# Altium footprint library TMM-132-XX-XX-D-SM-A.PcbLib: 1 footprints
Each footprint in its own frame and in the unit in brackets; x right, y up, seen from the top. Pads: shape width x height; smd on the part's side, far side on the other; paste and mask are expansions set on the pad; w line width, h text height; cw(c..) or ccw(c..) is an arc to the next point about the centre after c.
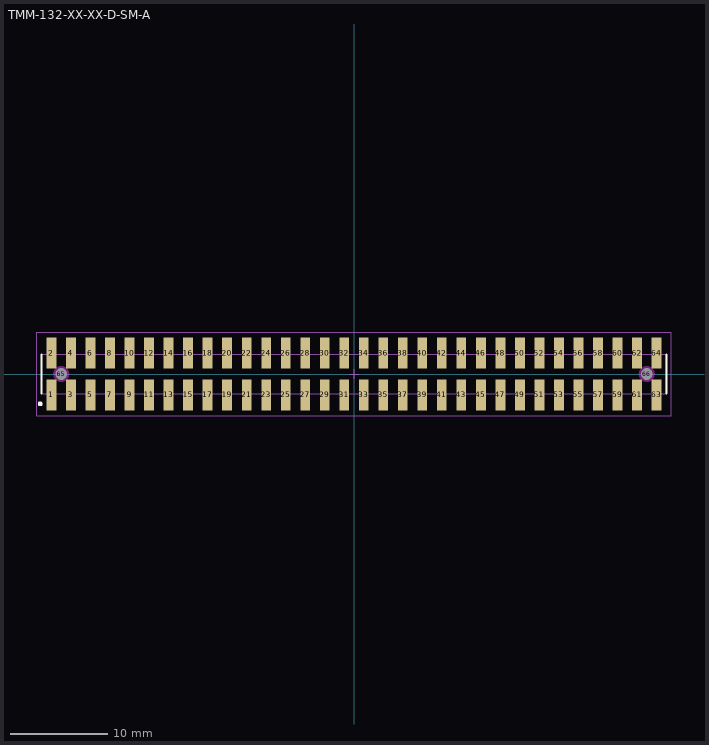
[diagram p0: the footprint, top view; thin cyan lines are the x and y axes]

## TMM-132-XX-XX-D-SM-A [mm] "2.00mm pitch, 64 pin, terminal strip; double row, w/alignment pins, SMT"
height 2.77
pads (66):
  rect 1x3.2 smd mask+0: 1(-31,-2.15) 2(-31,2.15) 3(-29,-2.15) 4(-29,2.15) 5(-27,-2.15) 6(-27,2.15) 7(-25,-2.15) 8(-25,2.15) 9(-23,-2.15) 10(-23,2.15) 11(-21,-2.15) 12(-21,2.15) 13(-19,-2.15) 14(-19,2.15) 15(-17,-2.15) 16(-17,2.15) 17(-15,-2.15) 18(-15,2.15) 19(-13,-2.15) 20(-13,2.15) 21(-11,-2.15) 22(-11,2.15) 23(-9,-2.15) 24(-9,2.15) 25(-7,-2.15) 26(-7,2.15) 27(-5,-2.15) 28(-5,2.15) 29(-3,-2.15) 30(-3,2.15) 31(-1,-2.15) 32(-1,2.15) 33(1,-2.15) 34(1,2.15) 35(3,-2.15) 36(3,2.15) 37(5,-2.15) 38(5,2.15) 39(7,-2.15) 40(7,2.15) 41(9,-2.15) 42(9,2.15) 43(11,-2.15) 44(11,2.15) 45(13,-2.15) 46(13,2.15) 47(15,-2.15) 48(15,2.15) 49(17,-2.15) 50(17,2.15) 51(19,-2.15) 52(19,2.15) 53(21,-2.15) 54(21,2.15) 55(23,-2.15) 56(23,2.15) 57(25,-2.15) 58(25,2.15) 59(27,-2.15) 60(27,2.15) 61(29,-2.15) 62(29,2.15) 63(31,-2.15) 64(31,2.15)
  round 1 hole 1.2 unplated mask+0: 65(-30,0) 66(30,0)
Top Overlay:
  circle w0.25: c-32.15,-3.05 r0.125
  lines w0.2: -32,-2 -32,2 ; 32,-2 32,2
Keep-Out Layer:
  pour cut-out: -29.193,0 -29.22,0.209 -29.301,0.403 -29.429,0.571 -29.596,0.699 -29.791,0.779 -30,0.807 -30.209,0.779 -30.403,0.699 -30.57,0.571 -30.699,0.403 -30.779,0.209 -30.807,0 -30.779,-0.209 -30.699,-0.403 -30.57,-0.571 -30.403,-0.699 -30.209,-0.779 -30,-0.807 -29.791,-0.779 -29.596,-0.699 -29.429,-0.571 -29.301,-0.403 -29.22,-0.209
  pour cut-out: 30.807,0 30.779,0.209 30.699,0.403 30.57,0.571 30.403,0.699 30.209,0.779 30,0.807 29.791,0.779 29.596,0.699 29.429,0.571 29.301,0.403 29.22,0.209 29.193,0 29.22,-0.209 29.301,-0.403 29.429,-0.571 29.596,-0.699 29.791,-0.779 30,-0.807 30.209,-0.779 30.403,-0.699 30.57,-0.571 30.699,-0.403 30.779,-0.209
Mechanical 12:
  lines w0.001: -32,-2 32,-2 32,2 -32,2 -32,-2
Mechanical 13:
  lines w0.1: -32,-2 32,-2 32,2 -32,2 -32,-2
  text ".Designator" at 0.127,-0.127 h1.52
Mechanical 15:
  lines w0.05: -0.5,0 0.5,0 ; 0,-0.5 0,0.5 ; -32.5,-4.3 32.5,-4.3 32.5,4.3 -32.5,4.3 -32.5,-4.3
